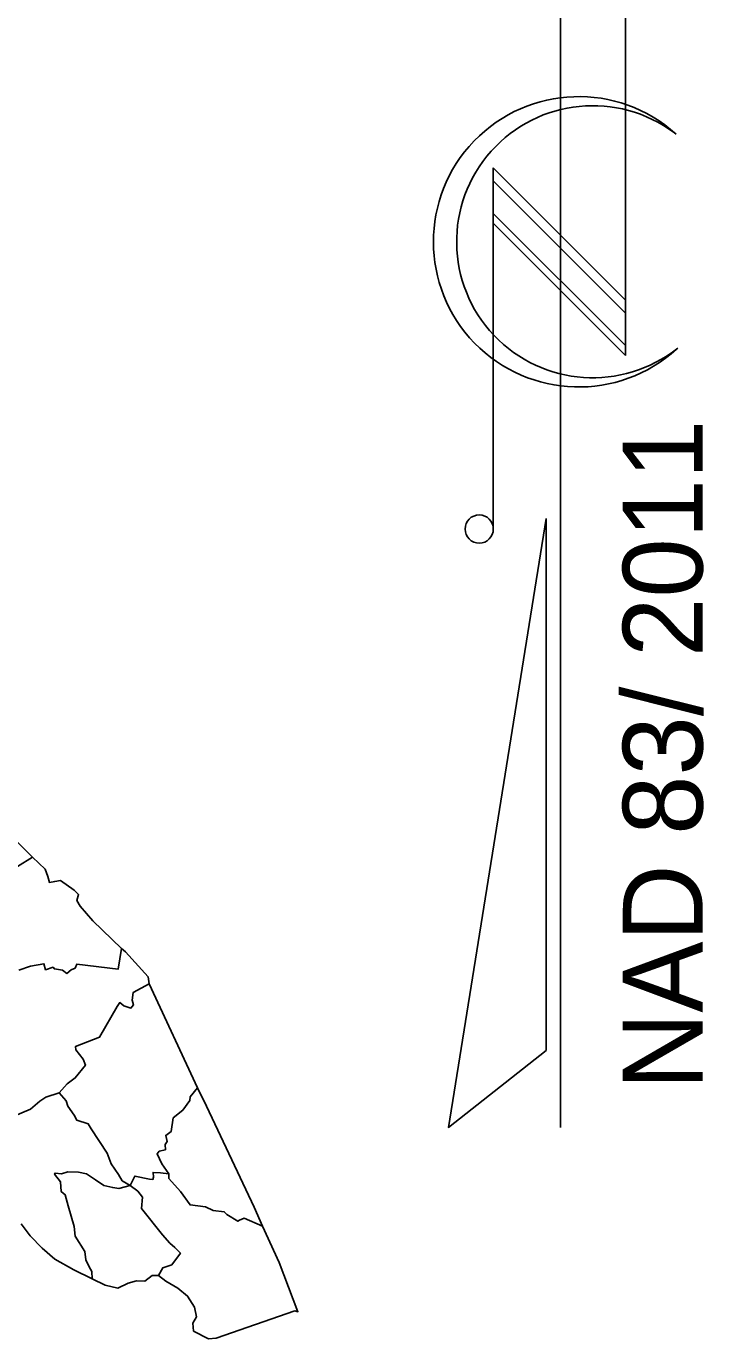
# Model space of a CAD drawing. Extents: x 442728 to 492797, y 479541 to 511293.
# Drawn here: x 470160 to 471115, y 502180 to 504031 of the extents above; entities that cross this region are included whole.
import ezdxf

# ---------------------------------------------------------------- set-up
doc = ezdxf.new("R2010")
doc.units = 0
for name, color, linetype in [('Default', 7, 'Continuous'), ('Prop Shade Medium', 7, 'Continuous'), ('Sheet North Arrow CELL', 7, 'Continuous')]:
    doc.layers.add(name, color=color, linetype=linetype)

msp = doc.modelspace()

# ---------------------------------------------------------------- linework, layer by layer
at = {"layer": 'Default'}
for points in [[(470137.9, 502889.9), (470168.8, 502859.1), (470126.4, 502832.6)], [(470153, 502341.6), (470165.6, 502324.7), (470182.6, 502307.3), (470200.2, 502292), (470227, 502277), (470253.1, 502264.3), (470271.3, 502255.5), (470289.3, 502251), (470303.8, 502257.9), (470315.6, 502261.5), (470327.5, 502260.8), (470337.4, 502268.8), (470346.5, 502269), (470357, 502261), (470373.6, 502251.1), (470387.5, 502239.8), (470397.3, 502224.1), (470400.3, 502210.7), (470395.1, 502201.6), (470396, 502190.6), (470417.3, 502179.7), (470428.1, 502180.5), (470539, 502219.1), (470543.1, 502217.9), (470516.6, 502287.4), (470493.4, 502338.7), (470481.5, 502365.5), (470414.1, 502507.8), (470401.4, 502533.8), (470333.5, 502680.4), (470331.8, 502690.4), (470299.9, 502725.6), (470294.2, 502730.2), (470254, 502769.2), (470236.2, 502790), (470231.4, 502797.9), (470233.9, 502806.1), (470227.8, 502812.4), (470208.5, 502826), (470200.3, 502824.8), (470192.8, 502823.3), (470190.3, 502831.8), (470186.7, 502842), (470168.8, 502859.1), (470137.9, 502889.9)], [(470126.4, 502832.6), (470168.8, 502859.1), (470186.7, 502842), (470190.3, 502831.8), (470192.8, 502823.3), (470200.3, 502824.8), (470208.5, 502826), (470227.8, 502812.4), (470233.9, 502806.1), (470231.4, 502797.9), (470236.2, 502790), (470254, 502769.2), (470294.2, 502730.2), (470289.5, 502700.9), (470231.6, 502708.1), (470229, 502702.4), (470223.6, 502700.1), (470217.1, 502695.1), (470211.4, 502699.7), (470199.9, 502701.3), (470198, 502703.8), (470187.4, 502700.1), (470184.9, 502708.7), (470166.3, 502705.1), (470149.6, 502699.6)], [(470227.8, 502812.4), (470233.9, 502806.1), (470231.4, 502797.9), (470236.2, 502790), (470254, 502769.2), (470294.2, 502730.2), (470299.9, 502725.6)], [(470149.6, 502699.6), (470166.3, 502705.1), (470184.9, 502708.7), (470187.4, 502700.1), (470198, 502703.8), (470199.9, 502701.3), (470211.4, 502699.7), (470217.1, 502695.1), (470223.6, 502700.1), (470229, 502702.4), (470231.6, 502708.1), (470289.5, 502700.9), (470294.2, 502730.2), (470299.9, 502725.6), (470331.8, 502690.4), (470333.5, 502680.4), (470310.9, 502668.1), (470309.2, 502657.1), (470311.1, 502650.8), (470307.6, 502646.1), (470297.5, 502649.3), (470291.9, 502653.8), (470288.5, 502648.5), (470263.5, 502605.1), (470229.4, 502591.9), (470230.2, 502587.2), (470240.3, 502574), (470243.4, 502565.6), (470229.2, 502547.7), (470217.6, 502539.3), (470206.6, 502526.7), (470187.6, 502520.4), (470179.4, 502514.9), (470166.3, 502503.5), (470141.7, 502493.1)], [(470216.2, 502515.2), (470206.6, 502526.7), (470217.6, 502539.3), (470229.2, 502547.7), (470243.4, 502565.6), (470240.3, 502574), (470230.2, 502587.2), (470229.4, 502591.9), (470263.5, 502605.1), (470288.5, 502648.5), (470291.9, 502653.8), (470297.5, 502649.3), (470307.6, 502646.1), (470311.1, 502650.8), (470309.2, 502657.1), (470310.9, 502668.1), (470333.5, 502680.4), (470401.4, 502533.8), (470391.2, 502520.8), (470390.9, 502515.7), (470380.9, 502502.2), (470367.1, 502491.2), (470364.4, 502471.8), (470356.8, 502466.4), (470358.9, 502457.7), (470355.8, 502453.7), (470356.2, 502446.3), (470347.6, 502444.4), (470344.5, 502440.3), (470351.2, 502426.2), (470361, 502412.3), (470349.5, 502413.8), (470338.9, 502414.4), (470339.7, 502407.8), (470338.8, 502404.4), (470333.8, 502404.8), (470313.4, 502409.2), (470306.4, 502395.9), (470295.2, 502402.5), (470290, 502411.5), (470279.9, 502426.5), (470274.1, 502441.6), (470251.4, 502475.9), (470247.5, 502482.8), (470231.2, 502487.9), (470227.8, 502495), (470218.5, 502507.8), (470216.2, 502515.2)], [(470344.5, 502440.3), (470347.6, 502444.4), (470356.2, 502446.3), (470355.8, 502453.7), (470358.9, 502457.7), (470356.8, 502466.4), (470364.4, 502471.8), (470367.1, 502491.2), (470380.9, 502502.2), (470390.9, 502515.7), (470391.2, 502520.8), (470401.4, 502533.8), (470414.1, 502507.8), (470481.5, 502365.5), (470493.4, 502338.7), (470467.2, 502350), (470460.8, 502346.8), (470458.2, 502345.4), (470443, 502355.1), (470439.3, 502358.9), (470423.5, 502360.4), (470412.7, 502365.8), (470391, 502368.5), (470377.8, 502387.5), (470361.2, 502405.6), (470361, 502412.3), (470351.2, 502426.2), (470344.5, 502440.3)], [(470141.7, 502493.1), (470166.3, 502503.5), (470179.4, 502514.9), (470187.6, 502520.4), (470206.6, 502526.7), (470216.2, 502515.2), (470218.5, 502507.8), (470227.8, 502495), (470231.2, 502487.9), (470247.5, 502482.8), (470251.4, 502475.9), (470274.1, 502441.6), (470279.9, 502426.5), (470290, 502411.5), (470295.2, 502402.5), (470306.4, 502395.9), (470290.5, 502391.7), (470282.1, 502392.9), (470269.5, 502396), (470257.9, 502403.7), (470244.9, 502412.2), (470233.7, 502414.5), (470218.8, 502415), (470209.8, 502412.3), (470200.8, 502413.4), (470200.1, 502411.9)], [(470200.1, 502411.9), (470208.2, 502401.2), (470209.4, 502387.2), (470215.1, 502382.7), (470219.2, 502367.1), (470227.5, 502337.8), (470229.1, 502324.5), (470242.5, 502303), (470244.3, 502291), (470248.6, 502281.1), (470252.4, 502274.7), (470253.1, 502264.3), (470227, 502277), (470200.2, 502292), (470182.6, 502307.3), (470165.6, 502324.7), (470153, 502341.6)], [(470306.4, 502395.9), (470317.4, 502388), (470323.8, 502379.3), (470322.5, 502363.4), (470352.3, 502326.3), (470362.7, 502314.5), (470369.5, 502308.4), (470377.5, 502300.3), (470365.3, 502284.1), (470352.5, 502279.6), (470346.5, 502269), (470337.4, 502268.8), (470327.5, 502260.8), (470315.6, 502261.5), (470303.8, 502257.9), (470289.3, 502251), (470271.3, 502255.5), (470253.1, 502264.3), (470252.4, 502274.7), (470248.6, 502281.1), (470244.3, 502291), (470242.5, 502303), (470229.1, 502324.5), (470227.5, 502337.8), (470219.2, 502367.1), (470215.1, 502382.7), (470209.4, 502387.2), (470208.2, 502401.2), (470200.1, 502411.9), (470200.8, 502413.4), (470209.8, 502412.3), (470218.8, 502415), (470233.7, 502414.5), (470244.9, 502412.2), (470257.9, 502403.7), (470269.5, 502396), (470282.1, 502392.9), (470290.5, 502391.7), (470306.4, 502395.9)], [(470306.4, 502395.9), (470313.4, 502409.2), (470333.8, 502404.8), (470338.8, 502404.4), (470339.7, 502407.8), (470338.9, 502414.4), (470349.5, 502413.8), (470361, 502412.3), (470361.2, 502405.6), (470377.8, 502387.5), (470391, 502368.5), (470412.7, 502365.8), (470423.5, 502360.4), (470439.3, 502358.9), (470443, 502355.1), (470458.2, 502345.4), (470460.8, 502346.8), (470467.2, 502350), (470493.4, 502338.7), (470516.6, 502287.4), (470543.1, 502217.9), (470539, 502219.1), (470428.1, 502180.5), (470417.3, 502179.7), (470396, 502190.6), (470395.1, 502201.6), (470400.3, 502210.7), (470397.3, 502224.1), (470387.5, 502239.8), (470373.6, 502251.1), (470357, 502261), (470346.5, 502269), (470352.5, 502279.6), (470365.3, 502284.1), (470377.5, 502300.3), (470369.5, 502308.4), (470362.7, 502314.5), (470352.3, 502326.3), (470322.5, 502363.4), (470323.8, 502379.3), (470317.4, 502388), (470306.4, 502395.9)]]:
    msp.add_lwpolyline(points, dxfattribs=at)
at = {"layer": 'Prop Shade Medium'}
for p, q in [((470391, 502368.5), (470377.8, 502387.5)), ((470323.8, 502379.3), (470322.5, 502363.4)), ((470322.5, 502363.4), (470352.3, 502326.3)), ((470412.7, 502365.8), (470391, 502368.5)), ((470493.4, 502338.7), (470467.2, 502350)), ((470516.6, 502287.4), (470493.4, 502338.7)), ((470369.5, 502308.4), (470377.5, 502300.3)), ((470377.5, 502300.3), (470365.3, 502284.1)), ((470352.5, 502279.6), (470346.5, 502269)), ((470365.3, 502284.1), (470352.5, 502279.6)), ((470543.1, 502217.9), (470516.6, 502287.4)), ((470397.3, 502224.1), (470400.3, 502210.7)), ((470400.3, 502210.7), (470395.1, 502201.6))]:
    msp.add_line(p, q, dxfattribs=at)
for points in [[(470333.8, 502404.8), (470313.4, 502409.2), (470306.4, 502395.9), (470317.4, 502388), (470323.8, 502379.3)], [(470338.9, 502414.4), (470339.7, 502407.8), (470338.8, 502404.4), (470333.8, 502404.8)], [(470361, 502412.3), (470349.5, 502413.8), (470338.9, 502414.4)], [(470377.8, 502387.5), (470361.2, 502405.6), (470361, 502412.3)], [(470458.2, 502345.4), (470443, 502355.1), (470439.3, 502358.9), (470423.5, 502360.4), (470412.7, 502365.8)], [(470467.2, 502350), (470460.8, 502346.8), (470458.2, 502345.4)], [(470352.3, 502326.3), (470362.7, 502314.5), (470369.5, 502308.4)], [(470346.5, 502269), (470357, 502261), (470373.6, 502251.1)], [(470373.6, 502251.1), (470387.5, 502239.8), (470397.3, 502224.1)], [(470395.1, 502201.6), (470396, 502190.6), (470417.3, 502179.7), (470428.1, 502180.5), (470539, 502219.1), (470543.1, 502217.9)]]:
    msp.add_lwpolyline(points, dxfattribs=at)
at = {"layer": 'Sheet North Arrow CELL'}
for p, q in [((470913.2, 502477.7), (470913.2, 504915.2)), ((471005.1, 504066.9), (471005.1, 503566.7)), ((471074.1, 503880.6), (471076.7, 503878.7)), ((471005.1, 503644.7), (470818.7, 503831.1)), ((470818.7, 503831.1), (470818.7, 503322.6)), ((471005.1, 503626.3), (470818.7, 503812.7)), ((470818.7, 503812.7), (470818.7, 503766.9)), ((471005.1, 503580.6), (470818.7, 503766.9)), ((470818.7, 503766.9), (471005.1, 503580.6)), ((471005.1, 503566.7), (470818.7, 503753.1)), ((471005.1, 503580.6), (471005.1, 503626.3))]:
    msp.add_line(p, q, dxfattribs=at)
msp.add_lwpolyline([(470893.3, 503336.4), (470755.3, 502477.7), (470893.3, 502586.4)], close=True, dxfattribs=at)
msp.add_circle((470798.8, 503321.8), 19.9, dxfattribs=at)
for centre, radius, start, end in [((470939.1, 503726.9), 204.8, 47.84, 312.3941), ((470958.9, 503727), 191.9, 53.095, 308.6287)]:
    msp.add_arc(centre, radius, start, end, dxfattribs=at)

# ---------------------------------------------------------------- texts
msp.add_text('NAD 83/ 2011', height=112.5, rotation=90, dxfattribs=at).set_placement((471113.8, 502531))

doc.saveas('drawing.dxf')
